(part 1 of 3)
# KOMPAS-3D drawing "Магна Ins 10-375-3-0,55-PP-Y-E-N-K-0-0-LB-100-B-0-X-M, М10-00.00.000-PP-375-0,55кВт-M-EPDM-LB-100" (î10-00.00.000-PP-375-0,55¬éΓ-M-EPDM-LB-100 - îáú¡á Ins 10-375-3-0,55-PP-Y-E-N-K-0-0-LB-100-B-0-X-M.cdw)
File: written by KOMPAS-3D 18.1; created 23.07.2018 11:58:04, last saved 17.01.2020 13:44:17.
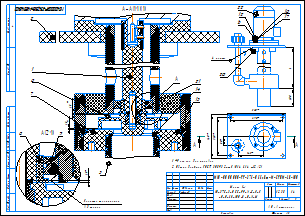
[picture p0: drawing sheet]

Sheet 1: A3, landscape

Document properties: Полное имя файла: ..\М10-00.00.000 - Магна Ins 10-C-N.a3d; Автор: Милов; Масса: 12.3778

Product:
- Part/product: Магна Ins 10-375-3-0,55-PP-Y-E-N-K-0-0-LB-100-B-0-X-M  | designation М10-00.00.000-PP-375-0,55кВт-M-EPDM-LB-100
    Масса: 12.3778
    source file: М10-00.00.000-PP-375-0,55кВт-M-EPDM-LB-100 - Магна Ins 10-375-3-0,55-PP-Y-E-N-K-0-0-LB-100-B-0-X-M.cdw, М10-00.00.000-PP-375-0,55кВт-M-EPDM-LB-100 - Магна Ins 10-375-3-0,55-PP-Y-E-N-K-0-0-LB-100-B-0-X-M.spw
  - Component [detail]: Крышка  | designation М10-00.00.002-01  | pos. 7
      Материал: Полипропилен  ГОСТ 26996-86 (density 900 kg/m3)
      Масса: 0.284697
      Раздел спецификации: Детали
      Форматы листов документа: 4xA4
      Примечание: @100~)4xA4
      Зона: 2A
      source file: ..\М10-00.00.002 - Крышка.cdw, ..\М10-00.00.002 - Крышка.m3d
  - Component [detail]: Импеллер Магна10  | designation М10-00.00.001  | pos. 6  | Масса: 0.169927; Раздел спецификации: Детали; Форматы листов документа: A3; Зона: 2A; source file: ..\М10-00.00.001 - Импеллер Магна10.m3d
  - Component [detail]: Защитная втулка  | designation М10-00.00.003  | pos. 8  | Масса: 0.0193569; Раздел спецификации: Детали; Форматы листов документа: A4; source file: ..\М10-00.00.003 - Защитная втулка.cdw, ..\М10-00.00.003 - Защитная втулка.m3d
  - Component [detail]: Втулка ответная  | designation М10А-00.00.003-01  | pos. 9  | Масса: 0.031838; Раздел спецификации: Детали; Форматы листов документа: A4; Примечание: Заим.; source file: ..\..\..\..\..\..\AquaProf\АкваProf 190\3Д модель\М10А-00.00.003 - Втулка ответная.m3d
  - Component [detail]: Всасывающая трубка 75  | designation L=100  | pos. 5
      Материал: Полипропилен  ГОСТ 26996-86 (density 900 kg/m3)
      Масса: 0.190378
      Раздел спецификации: Детали
      Форматы листов документа: 3xA3
      Примечание: @100~)3xA3
      Зона: 2A
      source file: ..\..\..\..\Магна ins 11\Магна N\3Д\Магна INS 11\Всасывающая трубка 75.m3d, ..\..\..\..\Магна ins 11\Магна N\3Д\Магна INS 11\Чертежи\М11-00.00.004-01 - Крышка.cdw
  - Component [standard]: Кольцо 058-064-36-1-0 ГОСТ 9833-73  | pos. 14
      Материал: Смесь резиновая ИРП-1068 ТУ 38-1051082-86 (density 1280 kg/m3)
      Масса: 0.00194
      Раздел спецификации: Стандартные изделия
      Примечание: EPDM
      Зона: 1A
      Рассекать на разрезах: no
      additional columns: 058-064-36-1-0
  - Component [standard]: Кольцо 125-130-25-1-0 ГОСТ 9833-73  | pos. 15
      Материал: Смесь резиновая ИРП-1068 ТУ 38-1051082-86 (density 1280 kg/m3)
      Масса: 0.00019
      Раздел спецификации: Стандартные изделия
      Примечание: EPDM
      Зона: 1A
      Рассекать на разрезах: no
      additional columns: 125-130-25-1-0
- Part/product: Магна Ins 10-375-3-0,75-PP-Y-V-N-K-0-0-L-0-B-0-X-M  | designation М10-00.00.000-PP-375-0,75кВт-M-Viton
    Масса: 15.6408
  - Component [detail]: Кольцо уплотнительное плоское 10-18-25  | designation Viton  | pos. 93  | Масса: 0.000562973; Раздел спецификации: Прочие изделия
  - Component [assembly]: Корпус полипропилен 375 0,75кВт  / с разъёмной муфтой  | designation М10-00.20.000-PP-375-0,75кВт-M  | pos. 2
      Материал: Полипропилен  ГОСТ 26996-86 (density 900 kg/m3)
      Масса: 5.65999
      Раздел спецификации: Сборочные единицы
      Форматы листов документа: 3xA3
      Примечание: @100~)3xA3@101~)3xA3
      source file: ..\М10-00.20.000 - Корпус.a3d
  - Component [assembly]: Вал  | designation М10-00.15.000-0,75кВт-375  | pos. 1
      Материал: Полипропилен  ГОСТ 26996-86 (density 900 kg/m3)
      Масса: 0.519317
      Раздел спецификации: Сборочные единицы
      Форматы листов документа: 2xA3
      Примечание: @100~)2xA3
      source file: ..\М10-00.15.000 - Вал.a3d
  - Component [detail]: Крышка  | designation М10-00.00.002  | pos. 4
      Материал: Полипропилен  ГОСТ 26996-86 (density 900 kg/m3)
      Масса: 0.324102
      Раздел спецификации: Детали
      Форматы листов документа: 4xA4
      Примечание: @100~)4xA4
      source file: ..\М10-00.00.002 - Крышка.m3d
  - Component [detail]: Импеллер Магна10  | designation М10-00.00.001  | pos. 3  | Масса: 0.169927; Раздел спецификации: Детали; Форматы листов документа: A3; source file: ..\М10-00.00.001 - Импеллер Магна10.m3d
  - Component [detail]: Защитная втулка  | designation М10-00.00.003  | pos. 5  | Масса: 0.0193569; Раздел спецификации: Детали; Форматы листов документа: A4; source file: ..\М10-00.00.003 - Защитная втулка.cdw, ..\М10-00.00.003 - Защитная втулка.m3d
  - Component [detail]: Втулка ответная  | designation М10А-00.00.003-01  | pos. 6  | Масса: 0.031838; Раздел спецификации: Детали; Форматы листов документа: A4; Примечание: Заим.; source file: ..\..\..\..\..\..\AquaProf\АкваProf 190\3Д модель\М10А-00.00.003 - Втулка ответная.m3d
  - Component [standard]: Шайба C.10.21 ГОСТ 11371-78  | qty 8  | pos. 11  | Материал: Сталь 12Х18Н10Т ГОСТ 5632-72 (density 1000 kg/m3); Масса: 0.003438; Раздел спецификации: Стандартные изделия; Рассекать на разрезах: no; additional columns: Сталь 12Х18Н10Т ГОСТ 5632-72
  - Component [standard]: Шайба 10 ГОСТ 6402-70  | qty 4  | pos. 10  | Масса: 0.00201; Раздел спецификации: Стандартные изделия; Примечание: Нерж.; Рассекать на разрезах: no; additional columns: 10; Без указания материала
  - Component [standard]: Гайка М10x1,25-6H(S16) ГОСТ 5915-70  | qty 4  | pos. 9  | Масса: 0.01022; Раздел спецификации: Стандартные изделия; Рассекать на разрезах: no; additional columns: М10x1,25-6H (S16); Сталь 12Х18Н10Т ГОСТ 5632-72
  - Component [standard]: Болт М10x1,25-6gx60 (S16) ГОСТ 7798-70  | qty 4  | pos. 8  | Масса: 0.0467; Раздел спецификации: Стандартные изделия; Рассекать на разрезах: no; additional columns: Сталь 12Х18Н10Т ГОСТ 5632-72
  - Component [detail]: Заглушка @2~25 FV PPR ф. "FV-Plast"  | qty 4  | pos. 12  | Материал: Полипропилен  ГОСТ 26996-86 (density 900 kg/m3); Масса: 0.0161976; Раздел спецификации: Прочие изделия
- Part/product: Магна Ins 10-425-3-0,55-PP-Y-E-N-K-0-0-L-0-B-0-X-R  | designation М10-00.00.000-PP-425-0,55кВт-R-EPDM
    Масса: 11.6152
  - Component [detail]: Втулка ответная  | designation М10А-00.00.003-01  | pos. 6  | Масса: 0.031838; Раздел спецификации: Детали; Форматы листов документа: A4; Примечание: Заим.; source file: ..\..\..\..\..\..\AquaProf\АкваProf 190\3Д модель\М10А-00.00.003 - Втулка ответная.m3d, ..\М10А-00.00.003-01 - Втулка ответная.cdw
  - Component [detail]: Защитная втулка  | designation М10-00.00.003  | pos. 5  | Масса: 0.0193569; Раздел спецификации: Детали; Форматы листов документа: A4; source file: ..\М10-00.00.003 - Защитная втулка.cdw, ..\М10-00.00.003 - Защитная втулка.m3d
  - Component [detail]: Импеллер Магна10  | designation М10-00.00.001  | pos. 3  | Масса: 0.169927; Раздел спецификации: Детали; Форматы листов документа: A3; source file: ..\М10-00.00.001 - Импеллер Магна10.cdw, ..\М10-00.00.001 - Импеллер Магна10.m3d
  - Component [detail]: Крышка  | designation М10-00.00.002  | pos. 4
      Материал: Полипропилен  ГОСТ 26996-86 (density 900 kg/m3)
      Масса: 0.324102
      Раздел спецификации: Детали
      Форматы листов документа: 4xA4
      Примечание: @100~)4xA4
      source file: ..\М10-00.00.002 - Крышка.cdw, ..\М10-00.00.002 - Крышка.m3d
  - Component [assembly]: Вал  | designation М10-00.15.000-0,55кВт-425  | pos. 1
      Материал: Полипропилен  ГОСТ 26996-86 (density 900 kg/m3)
      Масса: 0.580892
      Раздел спецификации: Сборочные единицы
      Форматы листов документа: 2xA3
      Примечание: @100~)2xA3
      source file: ..\М10-00.15.000 - Вал.a3d
  - Component [assembly]: Корпус полипропилен 425 0,55кВт  / с резьбовым переходником  | designation М10-00.20.000-PP-425-0,55кВт-R  | pos. 2  | Материал: Полипропилен  ГОСТ 26996-86 (density 900 kg/m3); Масса: 5.24529; Раздел спецификации: Сборочные единицы; Форматы листов документа: 3xA3; Примечание: @100~)3xA3@101~)3xA3
- Part/product: Магна Ins 10-425-3-0,55-PP-Y-E-N-K-0-0-L-0-B-0-X-M  | designation М10-00.00.000-PP-425-0,55кВт-M-EPDM
    Масса: 12.5317
  - Component [detail]: Втулка ответная  | designation М10А-00.00.003-01  | pos. 6  | Масса: 0.031838; Раздел спецификации: Детали; Форматы листов документа: A4; Примечание: Заим.; source file: ..\..\..\..\..\..\AquaProf\АкваProf 190\3Д модель\М10А-00.00.003 - Втулка ответная.m3d, ..\М10А-00.00.003-01 - Втулка ответная.cdw
  - Component [detail]: Защитная втулка  | designation М10-00.00.003  | pos. 5  | Масса: 0.0193569; Раздел спецификации: Детали; Форматы листов документа: A4; source file: ..\М10-00.00.003 - Защитная втулка.cdw, ..\М10-00.00.003 - Защитная втулка.m3d
  - Component [detail]: Импеллер Магна10  | designation М10-00.00.001  | pos. 3  | Масса: 0.169927; Раздел спецификации: Детали; Форматы листов документа: A3; source file: ..\М10-00.00.001 - Импеллер Магна10.cdw, ..\М10-00.00.001 - Импеллер Магна10.m3d
  - Component [detail]: Крышка  | designation М10-00.00.002  | pos. 4
      Материал: Полипропилен  ГОСТ 26996-86 (density 900 kg/m3)
      Масса: 0.324102
      Раздел спецификации: Детали
      Форматы листов документа: 4xA4
      Примечание: @100~)4xA4
      source file: ..\М10-00.00.002 - Крышка.cdw, ..\М10-00.00.002 - Крышка.m3d
  - Component [assembly]: Вал  | designation М10-00.15.000-0,55кВт-425  | pos. 1
      Материал: Полипропилен  ГОСТ 26996-86 (density 900 kg/m3)
      Масса: 0.580892
      Раздел спецификации: Сборочные единицы
      Форматы листов документа: 2xA3
      Примечание: @100~)2xA3
      source file: ..\М10-00.15.000 - Вал.a3d
  - Component [assembly]: Корпус полипропилен 425 0,55кВт  / с разъёмной муфтой  | designation М10-00.20.000-PP-425-0,55кВт-M  | pos. 2  | Материал: Полипропилен  ГОСТ 26996-86 (density 900 kg/m3); Масса: 6.1618; Раздел спецификации: Сборочные единицы; Форматы листов документа: 3xA3; Примечание: @100~)3xA3@101~)3xA3
- Part/product: Магна Ins 10-PP-425-0,55кВт  | designation М10-00.00.000-PP-425-0,55кВт
    Масса: 11.5823
  - Component [assembly]: Корпус полипропилен 425 0,55кВт  | designation М10-00.20.000-PP-425-0,55кВт  | pos. 2  | Материал: Полипропилен  ГОСТ 26996-86 (density 900 kg/m3); Масса: 5.21242; Раздел спецификации: Сборочные единицы; Форматы листов документа: 3xA3; Примечание: @100~)3xA3@101~)3xA3
  - Component [assembly]: Вал  | designation М10-00.15.000-0,55кВт-425  | pos. 1
      Материал: Полипропилен  ГОСТ 26996-86 (density 900 kg/m3)
      Масса: 0.580892
      Раздел спецификации: Сборочные единицы
      Форматы листов документа: 2xA3
      Примечание: @100~)2xA3
      source file: ..\М10-00.15.000 - Вал.a3d
  - Component [detail]: Крышка  | designation М10-00.00.002  | pos. 4
      Материал: Полипропилен  ГОСТ 26996-86 (density 900 kg/m3)
      Масса: 0.324102
      Раздел спецификации: Детали
      Форматы листов документа: 4xA4
      Примечание: @100~)4xA4
      source file: ..\М10-00.00.002 - Крышка.cdw, ..\М10-00.00.002 - Крышка.m3d
  - Component [detail]: Импеллер Магна10  | designation М10-00.00.001  | pos. 3  | Масса: 0.169927; Раздел спецификации: Детали; Форматы листов документа: A3; source file: ..\М10-00.00.001 - Импеллер Магна10.cdw, ..\М10-00.00.001 - Импеллер Магна10.m3d
  - Component [detail]: Защитная втулка  | designation М10-00.00.003  | pos. 5  | Масса: 0.0193569; Раздел спецификации: Детали; Форматы листов документа: A4; source file: ..\М10-00.00.003 - Защитная втулка.cdw, ..\М10-00.00.003 - Защитная втулка.m3d
  - Component [detail]: Втулка ответная  | designation М10А-00.00.003-01  | pos. 6  | Масса: 0.031838; Раздел спецификации: Детали; Форматы листов документа: A4; Примечание: Заим.; source file: ..\..\..\..\..\..\AquaProf\АкваProf 190\3Д модель\М10А-00.00.003 - Втулка ответная.m3d, ..\М10А-00.00.003-01 - Втулка ответная.cdw
- Part/product: Магна Ins 10-PP-425  | designation М10-00.00.000-PP-425
    Масса: 11.5823
  - Component [detail]: Втулка ответная  | designation М10А-00.00.003-01  | pos. 6  | Масса: 0.031838; Раздел спецификации: Детали; Форматы листов документа: A4; Примечание: Заим.; source file: ..\..\..\..\..\..\AquaProf\АкваProf 190\3Д модель\М10А-00.00.003 - Втулка ответная.m3d, ..\М10А-00.00.003-01 - Втулка ответная.cdw
  - Component [detail]: Защитная втулка  | designation М10-00.00.003  | pos. 5  | Масса: 0.0193569; Раздел спецификации: Детали; Форматы листов документа: A4; source file: ..\М10-00.00.003 - Защитная втулка.cdw, ..\М10-00.00.003 - Защитная втулка.m3d
  - Component [detail]: Импеллер Магна10  | designation М10-00.00.001  | pos. 3  | Масса: 0.169927; Раздел спецификации: Детали; Форматы листов документа: A3; source file: ..\М10-00.00.001 - Импеллер Магна10.cdw, ..\М10-00.00.001 - Импеллер Магна10.m3d
  - Component [detail]: Крышка  | designation М10-00.00.002  | pos. 4
      Материал: Полипропилен  ГОСТ 26996-86 (density 900 kg/m3)
      Масса: 0.324102
      Раздел спецификации: Детали
      Форматы листов документа: 4xA4
      Примечание: @100~)4xA4
      source file: ..\М10-00.00.002 - Крышка.cdw, ..\М10-00.00.002 - Крышка.m3d
  - Component [assembly]: Вал  | designation М10-00.15.000-0,55кВт-425  | pos. 1
      Материал: Полипропилен  ГОСТ 26996-86 (density 900 kg/m3)
      Масса: 0.580892
      Раздел спецификации: Сборочные единицы
      Форматы листов документа: 2xA3
      Примечание: @100~)2xA3
      source file: ..\М10-00.15.000 - Вал.a3d
- Part/product: Магна Ins 10-375-3-0,75-PP-Y-E-N-K-0-0-L-0-B-0-X-R  | designation М10-00.00.000-PP-375-0,75кВт-R-EPDM
    Масса: 14.7243
  - Component [detail]: Заглушка @2~25 FV PPR ф. "FV-Plast"  | qty 4  | pos. 12  | Материал: Полипропилен  ГОСТ 26996-86 (density 900 kg/m3); Масса: 0.0161976; Раздел спецификации: Прочие изделия
  - Component [standard]: Болт М10x1,25-6gx60 (S16) ГОСТ 7798-70  | qty 4  | pos. 8  | Масса: 0.0467; Раздел спецификации: Стандартные изделия; Рассекать на разрезах: no; additional columns: Сталь 12Х18Н10Т ГОСТ 5632-72
  - Component [standard]: Гайка М10x1,25-6H(S16) ГОСТ 5915-70  | qty 4  | pos. 9  | Масса: 0.01022; Раздел спецификации: Стандартные изделия; Рассекать на разрезах: no; additional columns: М10x1,25-6H (S16); Сталь 12Х18Н10Т ГОСТ 5632-72
  - Component [standard]: Шайба 10 ГОСТ 6402-70  | qty 4  | pos. 10  | Масса: 0.00201; Раздел спецификации: Стандартные изделия; Примечание: Нерж.; Рассекать на разрезах: no; additional columns: 10; Без указания материала
  - Component [standard]: Шайба C.10.21 ГОСТ 11371-78  | qty 8  | pos. 11  | Материал: Сталь 12Х18Н10Т ГОСТ 5632-72 (density 1000 kg/m3); Масса: 0.003438; Раздел спецификации: Стандартные изделия; Рассекать на разрезах: no; additional columns: Сталь 12Х18Н10Т ГОСТ 5632-72
  - Component [detail]: Втулка ответная  | designation М10А-00.00.003-01  | pos. 6  | Масса: 0.031838; Раздел спецификации: Детали; Форматы листов документа: A4; Примечание: Заим.; source file: ..\..\..\..\..\..\AquaProf\АкваProf 190\3Д модель\М10А-00.00.003 - Втулка ответная.m3d, ..\М10А-00.00.003-01 - Втулка ответная.cdw
  - Component [detail]: Защитная втулка  | designation М10-00.00.003  | pos. 5  | Масса: 0.0193569; Раздел спецификации: Детали; Форматы листов документа: A4; source file: ..\М10-00.00.003 - Защитная втулка.cdw, ..\М10-00.00.003 - Защитная втулка.m3d
  - Component [detail]: Импеллер Магна10  | designation М10-00.00.001  | pos. 3  | Масса: 0.169927; Раздел спецификации: Детали; Форматы листов документа: A3; source file: ..\М10-00.00.001 - Импеллер Магна10.cdw, ..\М10-00.00.001 - Импеллер Магна10.m3d
  - Component [detail]: Крышка  | designation М10-00.00.002  | pos. 4
      Материал: Полипропилен  ГОСТ 26996-86 (density 900 kg/m3)
      Масса: 0.324102
      Раздел спецификации: Детали
      Форматы листов документа: 4xA4
      Примечание: @100~)4xA4
      source file: ..\М10-00.00.002 - Крышка.cdw, ..\М10-00.00.002 - Крышка.m3d
  - Component [assembly]: Вал  | designation М10-00.15.000-0,75кВт  | pos. 1  | Материал: Полипропилен  ГОСТ 26996-86 (density 900 kg/m3); Масса: 0.807009; Раздел спецификации: Сборочные единицы; Форматы листов документа: 2xA3; Примечание: @100~)2xA3
  - Component [assembly]: Корпус полипропилен 375 0,75кВт  / с резьбовым переходником  | designation М10-00.20.000-PP-375-0,75кВт-R  | pos. 2  | Материал: Полипропилен  ГОСТ 26996-86 (density 900 kg/m3); Масса: 4.74348; Раздел спецификации: Сборочные единицы; Форматы листов документа: 3xA3; Примечание: @100~)3xA3@101~)3xA3
- Part/product: Магна Ins 10-375-3-0,75-PP-Y-E-N-K-0-0-L-0-B-0-X-M  | designation М10-00.00.000-PP-375-0,75кВт-M-EPDM
    Масса: 15.6408
  - Component [detail]: Заглушка @2~25 FV PPR ф. "FV-Plast"  | qty 4  | pos. 12  | Материал: Полипропилен  ГОСТ 26996-86 (density 900 kg/m3); Масса: 0.0161976; Раздел спецификации: Прочие изделия
  - Component [standard]: Болт М10x1,25-6gx60 (S16) ГОСТ 7798-70  | qty 4  | pos. 8  | Масса: 0.0467; Раздел спецификации: Стандартные изделия; Рассекать на разрезах: no; additional columns: Сталь 12Х18Н10Т ГОСТ 5632-72
  - Component [standard]: Гайка М10x1,25-6H(S16) ГОСТ 5915-70  | qty 4  | pos. 9  | Масса: 0.01022; Раздел спецификации: Стандартные изделия; Рассекать на разрезах: no; additional columns: М10x1,25-6H (S16); Сталь 12Х18Н10Т ГОСТ 5632-72
  - Component [standard]: Шайба 10 ГОСТ 6402-70  | qty 4  | pos. 10  | Масса: 0.00201; Раздел спецификации: Стандартные изделия; Примечание: Нерж.; Рассекать на разрезах: no; additional columns: 10; Без указания материала
  - Component [standard]: Шайба C.10.21 ГОСТ 11371-78  | qty 8  | pos. 11  | Материал: Сталь 12Х18Н10Т ГОСТ 5632-72 (density 1000 kg/m3); Масса: 0.003438; Раздел спецификации: Стандартные изделия; Рассекать на разрезах: no; additional columns: Сталь 12Х18Н10Т ГОСТ 5632-72
  - Component [detail]: Втулка ответная  | designation М10А-00.00.003-01  | pos. 6  | Масса: 0.031838; Раздел спецификации: Детали; Форматы листов документа: A4; Примечание: Заим.; source file: ..\..\..\..\..\..\AquaProf\АкваProf 190\3Д модель\М10А-00.00.003 - Втулка ответная.m3d, ..\М10А-00.00.003-01 - Втулка ответная.cdw
  - Component [detail]: Защитная втулка  | designation М10-00.00.003  | pos. 5  | Масса: 0.0193569; Раздел спецификации: Детали; Форматы листов документа: A4; source file: ..\М10-00.00.003 - Защитная втулка.cdw, ..\М10-00.00.003 - Защитная втулка.m3d
  - Component [detail]: Импеллер Магна10  | designation М10-00.00.001  | pos. 3  | Масса: 0.169927; Раздел спецификации: Детали; Форматы листов документа: A3; source file: ..\М10-00.00.001 - Импеллер Магна10.cdw, ..\М10-00.00.001 - Импеллер Магна10.m3d
  - Component [detail]: Крышка  | designation М10-00.00.002  | pos. 4
      Материал: Полипропилен  ГОСТ 26996-86 (density 900 kg/m3)
      Масса: 0.324102
      Раздел спецификации: Детали
      Форматы листов документа: 4xA4
      Примечание: @100~)4xA4
      source file: ..\М10-00.00.002 - Крышка.cdw, ..\М10-00.00.002 - Крышка.m3d
  - Component [assembly]: Вал  | designation М10-00.15.000-0,75кВт-375  | pos. 1
      Материал: Полипропилен  ГОСТ 26996-86 (density 900 kg/m3)
      Масса: 0.519317
      Раздел спецификации: Сборочные единицы
      Форматы листов документа: 2xA3
      Примечание: @100~)2xA3
      source file: ..\М10-00.15.000 - Вал.a3d
  - Component [assembly]: Корпус полипропилен 375 0,75кВт  / с разъёмной муфтой  | designation М10-00.20.000-PP-375-0,75кВт-M  | pos. 2
      Материал: Полипропилен  ГОСТ 26996-86 (density 900 kg/m3)
      Масса: 5.65999
      Раздел спецификации: Сборочные единицы
      Форматы листов документа: 3xA3
      Примечание: @100~)3xA3@101~)3xA3
      source file: ..\М10-00.20.000 - Корпус.a3d
- Part/product: Магна Ins 10-PP-375-0,75кВт  | designation М10-00.00.000-PP-375-0,75кВт
    Масса: 14.6914
  - Component [detail]: Электродвигатель 3ф. АИР 71А2 / 380В 0,75кВт 3000 об/мин 3081 DRIVE IEK / арт.DRV071-A2-000-8-3030  | pos. 356  | Масса: 8.3; Раздел спецификации: Прочие изделия; Примечание: IP55; source file: ..\..\..\..\..\..\1 ПКИ 3D\Двигатели\АИР\Электродвигатель 3ф. АИР 71А2 380В 0,75кВт 3000об_мин 3081 DRIVE IEK.m3d
  - Component [assembly]: Корпус полипропилен 375 0,75кВт  | designation М10-00.20.000-PP-375-0,75кВт  | pos. 2  | Материал: Полипропилен  ГОСТ 26996-86 (density 900 kg/m3); Масса: 4.71061; Раздел спецификации: Сборочные единицы; Форматы листов документа: 3xA3; Примечание: @100~)3xA3@101~)3xA3
  - Component [assembly]: Вал  | designation М10-00.15.000-0,75кВт  | pos. 1  | Материал: Полипропилен  ГОСТ 26996-86 (density 900 kg/m3); Масса: 0.807009; Раздел спецификации: Сборочные единицы; Форматы листов документа: 2xA3; Примечание: @100~)2xA3
  - Component [detail]: Крышка  | designation М10-00.00.002  | pos. 4
      Материал: Полипропилен  ГОСТ 26996-86 (density 900 kg/m3)
      Масса: 0.324102
      Раздел спецификации: Детали
      Форматы листов документа: 4xA4
      Примечание: @100~)4xA4
      source file: ..\М10-00.00.002 - Крышка.cdw, ..\М10-00.00.002 - Крышка.m3d
  - Component [detail]: Импеллер Магна10  | designation М10-00.00.001  | pos. 3  | Масса: 0.169927; Раздел спецификации: Детали; Форматы листов документа: A3; source file: ..\М10-00.00.001 - Импеллер Магна10.cdw, ..\М10-00.00.001 - Импеллер Магна10.m3d
  - Component [detail]: Защитная втулка  | designation М10-00.00.003  | pos. 5  | Масса: 0.0193569; Раздел спецификации: Детали; Форматы листов документа: A4; source file: ..\М10-00.00.003 - Защитная втулка.cdw, ..\М10-00.00.003 - Защитная втулка.m3d
  - Component [detail]: Втулка ответная  | designation М10А-00.00.003-01  | pos. 6  | Масса: 0.031838; Раздел спецификации: Детали; Форматы листов документа: A4; Примечание: Заим.; source file: ..\..\..\..\..\..\AquaProf\АкваProf 190\3Д модель\М10А-00.00.003 - Втулка ответная.m3d, ..\М10А-00.00.003-01 - Втулка ответная.cdw
  - Component [standard]: Шайба C.10.21 ГОСТ 11371-78  | qty 8  | pos. 11  | Материал: Сталь 12Х18Н10Т ГОСТ 5632-72 (density 1000 kg/m3); Масса: 0.003438; Раздел спецификации: Стандартные изделия; Рассекать на разрезах: no; additional columns: Сталь 12Х18Н10Т ГОСТ 5632-72
  - Component [standard]: Шайба 10 ГОСТ 6402-70  | qty 4  | pos. 10  | Масса: 0.00201; Раздел спецификации: Стандартные изделия; Примечание: Нерж.; Рассекать на разрезах: no; additional columns: 10; Без указания материала
  - Component [standard]: Гайка М10x1,25-6H(S16) ГОСТ 5915-70  | qty 4  | pos. 9  | Масса: 0.01022; Раздел спецификации: Стандартные изделия; Рассекать на разрезах: no; additional columns: М10x1,25-6H (S16); Сталь 12Х18Н10Т ГОСТ 5632-72
  - Component [standard]: Болт М10x1,25-6gx60 (S16) ГОСТ 7798-70  | qty 4  | pos. 8  | Масса: 0.0467; Раздел спецификации: Стандартные изделия; Рассекать на разрезах: no; additional columns: Сталь 12Х18Н10Т ГОСТ 5632-72
  - Component [detail]: Заглушка @2~25 FV PPR ф. "FV-Plast"  | qty 4  | pos. 12  | Материал: Полипропилен  ГОСТ 26996-86 (density 900 kg/m3); Масса: 0.0161976; Раздел спецификации: Прочие изделия
- Part/product: Магна Ins 10-375-3-0,55-PP-Y-E-N-K-0-0-L-0-B-0-X-M  | designation М10-00.00.000-PP-375-0,55кВт-M-EPDM
    Масса: 12.2247
  - Component [detail]: Электродвигатель АИР 63В2 / IM 3081 0,55кВт 3000 об/мин  | pos. 14  | Масса: 5.02; Раздел спецификации: Прочие изделия; Примечание: IP55; source file: ..\..\..\..\..\..\1 ПКИ 3D\Двигатели\АИР\Электродвигатель АИР 63В2 IM 3081 0,55кВт 3000 об..m3d
  - Component [detail]: Втулка ответная  | designation М10А-00.00.003-01  | pos. 6  | Масса: 0.031838; Раздел спецификации: Детали; Форматы листов документа: A4; Примечание: Заим.; source file: ..\..\..\..\..\..\AquaProf\АкваProf 190\3Д модель\М10А-00.00.003 - Втулка ответная.m3d, ..\М10А-00.00.003-01 - Втулка ответная.cdw
  - Component [detail]: Защитная втулка  | designation М10-00.00.003  | pos. 5  | Масса: 0.0193569; Раздел спецификации: Детали; Форматы листов документа: A4; source file: ..\М10-00.00.003 - Защитная втулка.cdw, ..\М10-00.00.003 - Защитная втулка.m3d
  - Component [detail]: Импеллер Магна10  | designation М10-00.00.001  | pos. 3  | Масса: 0.169927; Раздел спецификации: Детали; Форматы листов документа: A3; source file: ..\М10-00.00.001 - Импеллер Магна10.cdw, ..\М10-00.00.001 - Импеллер Магна10.m3d
  - Component [detail]: Крышка  | designation М10-00.00.002  | pos. 4
      Материал: Полипропилен  ГОСТ 26996-86 (density 900 kg/m3)
      Масса: 0.324102
      Раздел спецификации: Детали
      Форматы листов документа: 4xA4
      Примечание: @100~)4xA4
      source file: ..\М10-00.00.002 - Крышка.cdw, ..\М10-00.00.002 - Крышка.m3d
  - Component [assembly]: Вал  | designation М10-00.15.000-0,55кВт-375  | pos. 1
      Материал: Полипропилен  ГОСТ 26996-86 (density 900 kg/m3)
      Масса: 0.519317
      Раздел спецификации: Сборочные единицы
      Форматы листов документа: 2xA3
      Примечание: @100~)2xA3
      source file: ..\М10-00.15.000 - Вал.a3d
  - Component [assembly]: Корпус полипропилен 375 0,55 кВт  / с разъёмной муфтой  | designation М10-00.20.000-PP-375-0,55кВт-M  | pos. 2
      Материал: Полипропилен  ГОСТ 26996-86 (density 900 kg/m3)
      Масса: 5.91637
      Раздел спецификации: Сборочные единицы
      Форматы листов документа: 3xA3
      Примечание: @100~)3xA3@101~)3xA3
      source file: ..\М10-00.20.000 - Корпус.a3d
- Part/product: Магна Ins 10-C-N  | designation М10-00.00.000
    Масса: 11.2753
    source file: ..\М10-00.00.000 - Магна Ins 10-C-N.cdw
  - Component: Шайба C.10.21 ГОСТ 11371-78  | pos. 11  | Материал: Сталь 12Х18Н10Т ГОСТ 5632-72; Масса: 0.0034; Раздел спецификации: Стандартные изделия
  - Component [detail]: Заглушка @2~20 FV PPR ф. "FV-Plast"  | qty 4  | pos. 12  | Масса: 0.0187746; Раздел спецификации: Прочие изделия; source file: ..\Заглушка ф20 FV PPR ф. FV-Plast.m3d
  - Component [standard]: Болт М8-6gx55.21.12Х18Н10Т ГОСТ 7798-70  | qty 4  | pos. 8  | Материал: Сталь 12Х18Н10Т ГОСТ 5632-72 (density 1000 kg/m3); Масса: 0.02699; Раздел спецификации: Стандартные изделия; additional columns: Сталь 12Х18Н10Т ГОСТ 5632-72; source file: C:\Program Files\ASCON\KOMPAS-3D v18\Libs\PartLib\DATA\VAULT\methods\kompas\3d\PLib_Bolt_1_900.m3d
  - Component [standard]: Гайка М8-6H.21.12Х18Н10Т ГОСТ 5915-70  | qty 4  | pos. 9  | Материал: Сталь 12Х18Н10Т ГОСТ 5632-72 (density 1000 kg/m3); Масса: 0.005548; Раздел спецификации: Стандартные изделия; additional columns: Сталь 12Х18Н10Т ГОСТ 5632-72; source file: C:\Program Files\ASCON\KOMPAS-3D v18\Libs\PartLib\DATA\VAULT\methods\kompas\3d\PLib_Nut_OST92_900.m3d
  - Component [standard]: Шайба 8 ГОСТ 6402-70  | qty 4  | pos. 10  | Масса: 0.001034; Раздел спецификации: Стандартные изделия; Примечание: Нерж.; additional columns: 8; Без указания материала; source file: C:\Program Files\ASCON\KOMPAS-3D v18\Libs\PartLib\DATA\VAULT\methods\kompas\3d\PLib_Washer_2_712.m3d
  - Component [standard]: Шайба C.8.21 ГОСТ 11371-78  | qty 8  | pos. 11  | Материал: Сталь 12Х18Н10Т ГОСТ 5632-72 (density 1000 kg/m3); Масса: 0.001725; Раздел спецификации: Стандартные изделия; additional columns: Сталь 12Х18Н10Т ГОСТ 5632-72; source file: C:\Program Files\ASCON\KOMPAS-3D v18\Libs\PartLib\DATA\VAULT\methods\kompas\3d\PLib_Washer_1_712.m3d
  - Component [detail]: Втулка ответная  | designation М10А-00.00.003-01  | pos. 6  | Масса: 0.031838; Раздел спецификации: Детали; Форматы листов документа: A4; Примечание: Заим.; source file: ..\..\..\..\..\..\AquaProf\АкваProf 190\3Д модель\М10А-00.00.003 - Втулка ответная.m3d, ..\М10А-00.00.003-01 - Втулка ответная.cdw
  - Component [detail]: Защитная втулка  | designation М10-00.00.003  | pos. 5  | Масса: 0.0193569; Раздел спецификации: Детали; Форматы листов документа: A4; source file: ..\М10-00.00.003 - Защитная втулка.cdw, ..\М10-00.00.003 - Защитная втулка.m3d
  - Component [detail]: Импеллер Магна10  | designation М10-00.00.001  | pos. 3  | Масса: 0.169927; Раздел спецификации: Детали; Форматы листов документа: A3; source file: ..\М10-00.00.001 - Импеллер Магна10.cdw, ..\М10-00.00.001 - Импеллер Магна10.m3d
  - Component [detail]: Крышка  | designation М10-00.00.002  | pos. 4
      Материал: Полипропилен  ГОСТ 26996-86 (density 900 kg/m3)
      Масса: 0.324102
      Раздел спецификации: Детали
      Форматы листов документа: 4xA4
      Примечание: @100~)4xA4
      source file: ..\М10-00.00.002 - Крышка.cdw, ..\М10-00.00.002 - Крышка.m3d
  - Component [assembly]: Вал  | designation М10-00.15.000  | pos. 1
      Материал: Полипропилен  ГОСТ 26996-86 (density 900 kg/m3)
      Масса: 0.519317
      Раздел спецификации: Сборочные единицы
      Форматы листов документа: 2xA3
      Примечание: @100~)2xA3
      source file: ..\М10-00.15.000 - Вал.a3d, ..\М10-00.15.000 - Вал.cdw
  - Component [detail]: Электродвигатель  / IM 3081 3000 об/мин IP55  | pos. 14  | Масса: 5.02; Раздел спецификации: Прочие изделия; Примечание: См. заказ; source file: ..\..\..\..\..\..\1 ПКИ 3D\Двигатели\АИР\Двигатель без габарита в СП\Электродвигатель АИР 63В2 IM 3081 0,55кВт 3000 об..m3d
  - Component [assembly]: Корпус  | designation М10-00.20.000  | pos. 2
      Материал: Полипропилен  ГОСТ 26996-86 (density 900 kg/m3)
      Масса: 4.96698
      Раздел спецификации: Сборочные единицы
      Форматы листов документа: 3xA3
      Примечание: @100~)3xA3@101~)3xA3
      source file: ..\М10-00.20.000 - Корпус.a3d, ..\М10-00.20.000 - Корпус.cdw
  - Component [detail]: Кольцо уплотнительное плоское 10-18-25  | designation EPDM  | pos. 93  | Масса: 0.000562973; Раздел спецификации: Прочие изделия; source file: ..\..\..\..\..\..\1 ПКИ 3D\РТИ\Кольца уплотнительные  плоские\Кольцо уплотнительное плоское 10-18-25 ЕPDM.m3d
- Part/product: Магна Ins 10-PP  | designation М10-00.00.000-PP
    Масса: 11.2753
  - Component [assembly]: Вал  | designation М10-00.15.000  | pos. 1
      Материал: Полипропилен  ГОСТ 26996-86 (density 900 kg/m3)
      Масса: 0.519317
      Раздел спецификации: Сборочные единицы
      Форматы листов документа: 2xA3
      Примечание: @100~)2xA3
      source file: ..\М10-00.15.000 - Вал.a3d, ..\М10-00.15.000 - Вал.cdw
  - Component [detail]: Крышка  | designation М10-00.00.002  | pos. 4
      Материал: Полипропилен  ГОСТ 26996-86 (density 900 kg/m3)
      Масса: 0.324102
      Раздел спецификации: Детали
      Форматы листов документа: 4xA4
      Примечание: @100~)4xA4
      source file: ..\М10-00.00.002 - Крышка.cdw, ..\М10-00.00.002 - Крышка.m3d
  - Component [detail]: Защитная втулка  | designation М10-00.00.003  | pos. 5  | Масса: 0.0193569; Раздел спецификации: Детали; Форматы листов документа: A4; source file: ..\М10-00.00.003 - Защитная втулка.cdw, ..\М10-00.00.003 - Защитная втулка.m3d
  - Component [detail]: Втулка ответная  | designation М10А-00.00.003-01  | pos. 6  | Масса: 0.031838; Раздел спецификации: Детали; Форматы листов документа: A4; Примечание: Заим.; source file: ..\..\..\..\..\..\AquaProf\АкваProf 190\3Д модель\М10А-00.00.003 - Втулка ответная.m3d, ..\М10А-00.00.003-01 - Втулка ответная.cdw
- Part/product: Магна Ins 10-PP-375  | designation М10-00.00.000-PP-375
    Масса: 11.2753
  - Component [detail]: Втулка ответная  | designation М10А-00.00.003-01  | pos. 6  | Масса: 0.031838; Раздел спецификации: Детали; Форматы листов документа: A4; Примечание: Заим.; source file: ..\..\..\..\..\..\AquaProf\АкваProf 190\3Д модель\М10А-00.00.003 - Втулка ответная.m3d, ..\М10А-00.00.003-01 - Втулка ответная.cdw
  - Component [detail]: Защитная втулка  | designation М10-00.00.003  | pos. 5  | Масса: 0.0193569; Раздел спецификации: Детали; Форматы листов документа: A4; source file: ..\М10-00.00.003 - Защитная втулка.cdw, ..\М10-00.00.003 - Защитная втулка.m3d
  - Component [detail]: Импеллер Магна10  | designation М10-00.00.001  | pos. 3  | Масса: 0.169927; Раздел спецификации: Детали; Форматы листов документа: A3; source file: ..\М10-00.00.001 - Импеллер Магна10.cdw, ..\М10-00.00.001 - Импеллер Магна10.m3d
  - Component [detail]: Крышка  | designation М10-00.00.002  | pos. 4
      Материал: Полипропилен  ГОСТ 26996-86 (density 900 kg/m3)
      Масса: 0.324102
      Раздел спецификации: Детали
      Форматы листов документа: 4xA4
      Примечание: @100~)4xA4
      source file: ..\М10-00.00.002 - Крышка.cdw, ..\М10-00.00.002 - Крышка.m3d
  - Component [assembly]: Вал  | designation М10-00.15.000  | pos. 1
      Материал: Полипропилен  ГОСТ 26996-86 (density 900 kg/m3)
      Масса: 0.519317
      Раздел спецификации: Сборочные единицы
      Форматы листов документа: 2xA3
      Примечание: @100~)2xA3
      source file: ..\М10-00.15.000 - Вал.a3d, ..\М10-00.15.000 - Вал.cdw
- Part/product: Магна Ins 10-PP-375-0,55кВт  | designation М10-00.00.000-PP-375-0,55кВт
    Масса: 11.2753
  - Component [detail]: Электродвигатель АИР 63В2 / IM 3081 0,55кВт 3000 об/мин  | pos. 321  | Масса: 5.02; Раздел спецификации: Прочие изделия; Примечание: IP55; source file: ..\..\..\..\..\..\1 ПКИ 3D\Двигатели\АИР\Электродвигатель АИР 63В2 IM 3081 0,55кВт 3000 об..m3d
  - Component [assembly]: Корпус полипропилен 375 0,55 кВт  | designation М10-00.20.000-PP-375-0,55кВт  | pos. 2  | Материал: Полипропилен  ГОСТ 26996-86 (density 900 kg/m3); Масса: 4.96698; Раздел спецификации: Сборочные единицы; Форматы листов документа: 3xA3; Примечание: @100~)3xA3@101~)3xA3
  - Component [assembly]: Вал  | designation М10-00.15.000-0,55кВт-375  | pos. 1
      Материал: Полипропилен  ГОСТ 26996-86 (density 900 kg/m3)
      Масса: 0.519317
      Раздел спецификации: Сборочные единицы
      Форматы листов документа: 2xA3
      Примечание: @100~)2xA3
      source file: ..\М10-00.15.000 - Вал.a3d
  - Component [detail]: Крышка  | designation М10-00.00.002  | pos. 4
      Материал: Полипропилен  ГОСТ 26996-86 (density 900 kg/m3)
      Масса: 0.324102
      Раздел спецификации: Детали
      Форматы листов документа: 4xA4
      Примечание: @100~)4xA4
      source file: ..\М10-00.00.002 - Крышка.cdw, ..\М10-00.00.002 - Крышка.m3d
  - Component [detail]: Импеллер Магна10  | designation М10-00.00.001  | pos. 3  | Масса: 0.169927; Раздел спецификации: Детали; Форматы листов документа: A3; source file: ..\М10-00.00.001 - Импеллер Магна10.cdw, ..\М10-00.00.001 - Импеллер Магна10.m3d
  - Component [detail]: Защитная втулка  | designation М10-00.00.003  | pos. 5  | Масса: 0.0193569; Раздел спецификации: Детали; Форматы листов документа: A4; source file: ..\М10-00.00.003 - Защитная втулка.cdw, ..\М10-00.00.003 - Защитная втулка.m3d
  - Component [detail]: Втулка ответная  | designation М10А-00.00.003-01  | pos. 6  | Масса: 0.031838; Раздел спецификации: Детали; Форматы листов документа: A4; Примечание: Заим.; source file: ..\..\..\..\..\..\AquaProf\АкваProf 190\3Д модель\М10А-00.00.003 - Втулка ответная.m3d, ..\М10А-00.00.003-01 - Втулка ответная.cdw
- Part/product: Магна Ins 10-375-3-0,55-PP-Y-E-N-K-0-0-L-0-B-0-X-R  | designation М10-00.00.000-PP-375-0,55кВт-R-EPDM
    Масса: 11.3082
  - Component [detail]: Электродвигатель АИР 63В2 / IM 3081 0,55кВт 3000 об/мин  | pos. 14  | Масса: 5.02; Раздел спецификации: Прочие изделия; Примечание: IP55; source file: ..\..\..\..\..\..\1 ПКИ 3D\Двигатели\АИР\Электродвигатель АИР 63В2 IM 3081 0,55кВт 3000 об..m3d
  - Component [detail]: Заглушка @2~20 FV PPR ф. "FV-Plast"  | pos. 12  | Масса: 0.0187746; Раздел спецификации: Прочие изделия; source file: ..\Заглушка ф20 FV PPR ф. FV-Plast.m3d
  - Component [detail]: Втулка ответная  | designation М10А-00.00.003-01  | pos. 6  | Масса: 0.031838; Раздел спецификации: Детали; Форматы листов документа: A4; Примечание: Заим.; source file: ..\..\..\..\..\..\AquaProf\АкваProf 190\3Д модель\М10А-00.00.003 - Втулка ответная.m3d, ..\М10А-00.00.003-01 - Втулка ответная.cdw
  - Component [detail]: Защитная втулка  | designation М10-00.00.003  | pos. 5  | Масса: 0.0193569; Раздел спецификации: Детали; Форматы листов документа: A4; source file: ..\М10-00.00.003 - Защитная втулка.cdw, ..\М10-00.00.003 - Защитная втулка.m3d
  - Component [detail]: Импеллер Магна10  | designation М10-00.00.001  | pos. 3  | Масса: 0.169927; Раздел спецификации: Детали; Форматы листов документа: A3; source file: ..\М10-00.00.001 - Импеллер Магна10.cdw, ..\М10-00.00.001 - Импеллер Магна10.m3d
  - Component [detail]: Крышка  | designation М10-00.00.002  | pos. 4
      Материал: Полипропилен  ГОСТ 26996-86 (density 900 kg/m3)
      Масса: 0.324102
      Раздел спецификации: Детали
      Форматы листов документа: 4xA4
      Примечание: @100~)4xA4
      source file: ..\М10-00.00.002 - Крышка.cdw, ..\М10-00.00.002 - Крышка.m3d
  - Component [assembly]: Вал  | designation М10-00.15.000-0,55кВт-375  | pos. 1
      Материал: Полипропилен  ГОСТ 26996-86 (density 900 kg/m3)
      Масса: 0.519317
      Раздел спецификации: Сборочные единицы
      Форматы листов документа: 2xA3
      Примечание: @100~)2xA3
      source file: ..\М10-00.15.000 - Вал.a3d
  - Component [assembly]: Корпус полипропилен 375 0,55 кВт  / с резьбовым переходником  | designation М10-00.20.000-PP-375-0,55кВт-R  | pos. 2
      Материал: Полипропилен  ГОСТ 26996-86 (density 900 kg/m3)
      Масса: 4.99986
      Раздел спецификации: Сборочные единицы
      Форматы листов документа: 3xA3
      Примечание: @100~)3xA3@101~)3xA3
      source file: ..\М10-00.20.000 - Корпус.a3d
  - Component [detail]: Кольцо уплотнительное плоское 10-18-25  | designation EPDM  | pos. 13  | Масса: 0.000562973; Раздел спецификации: Прочие изделия; source file: ..\..\..\..\..\..\1 ПКИ 3D\РТИ\Кольца уплотнительные  плоские\Кольцо уплотнительное плоское 10-18-25 ЕPDM.m3d
- Part/product: Магна Ins 10-PP-375-1,1кВт  | designation М10-00.00.000-PP-375-1,1кВт
    Масса: 14.4037
  - Component [detail]: Электродвигатель / АИР 71B2 IM 3081 IP55 ф."Элком"  | pos. 14  | Масса: 8.3; Раздел спецификации: Прочие изделия; Примечание: См. заказ
  - Component [assembly]: Вал  | designation М10-00.15.000  | pos. 1
      Материал: Полипропилен  ГОСТ 26996-86 (density 900 kg/m3)
      Масса: 0.519317
      Раздел спецификации: Сборочные единицы
      Форматы листов документа: 2xA3
      Примечание: @100~)2xA3
      source file: ..\М10-00.15.000 - Вал.a3d, ..\М10-00.15.000 - Вал.cdw
  - Component [detail]: Крышка  | designation М10-00.00.002  | pos. 4
      Материал: Полипропилен  ГОСТ 26996-86 (density 900 kg/m3)
      Масса: 0.324102
      Раздел спецификации: Детали
      Форматы листов документа: 4xA4
      Примечание: @100~)4xA4
      source file: ..\М10-00.00.002 - Крышка.cdw, ..\М10-00.00.002 - Крышка.m3d
  - Component [detail]: Импеллер Магна10  | designation М10-00.00.001  | pos. 3  | Масса: 0.169927; Раздел спецификации: Детали; Форматы листов документа: A3; source file: ..\М10-00.00.001 - Импеллер Магна10.cdw, ..\М10-00.00.001 - Импеллер Магна10.m3d
  - Component [detail]: Защитная втулка  | designation М10-00.00.003  | pos. 5  | Масса: 0.0193569; Раздел спецификации: Детали; Форматы листов документа: A4; source file: ..\М10-00.00.003 - Защитная втулка.cdw, ..\М10-00.00.003 - Защитная втулка.m3d
  - Component [detail]: Втулка ответная  | designation М10А-00.00.003-01  | pos. 6  | Масса: 0.031838; Раздел спецификации: Детали; Форматы листов документа: A4; Примечание: Заим.; source file: ..\..\..\..\..\..\AquaProf\АкваProf 190\3Д модель\М10А-00.00.003 - Втулка ответная.m3d, ..\М10А-00.00.003-01 - Втулка ответная.cdw
  - Component [standard]: Шайба C.10.21 ГОСТ 11371-78  | qty 8  | pos. 11  | Материал: Сталь 12Х18Н10Т ГОСТ 5632-72 (density 1000 kg/m3); Масса: 0.003438; Раздел спецификации: Стандартные изделия; Рассекать на разрезах: no; additional columns: Сталь 12Х18Н10Т ГОСТ 5632-72
  - Component [standard]: Шайба 10 ГОСТ 6402-70  | qty 4  | pos. 10  | Масса: 0.00201; Раздел спецификации: Стандартные изделия; Примечание: Нерж.; Рассекать на разрезах: no; additional columns: 10; Без указания материала
  - Component [standard]: Гайка М10x1,25-6H(S16) ГОСТ 5915-70  | qty 4  | pos. 9  | Масса: 0.01022; Раздел спецификации: Стандартные изделия; Рассекать на разрезах: no; additional columns: М10x1,25-6H (S16); Сталь 12Х18Н10Т ГОСТ 5632-72
  - Component [standard]: Болт М10x1,25-6gx60 (S16) ГОСТ 7798-70  | qty 4  | pos. 8  | Масса: 0.0467; Раздел спецификации: Стандартные изделия; Рассекать на разрезах: no; additional columns: Сталь 12Х18Н10Т ГОСТ 5632-72
  - Component [detail]: Заглушка @2~25 FV PPR ф. "FV-Plast"  | qty 4  | pos. 12  | Материал: Полипропилен  ГОСТ 26996-86 (density 900 kg/m3); Масса: 0.0161976; Раздел спецификации: Прочие изделия
- Part/product: Магна Ins 10-PP-475  | designation М10-00.00.000-PP-475
    Масса: 11.8893
  - Component [detail]: Втулка ответная  | designation М10А-00.00.003-01  | pos. 6  | Масса: 0.031838; Раздел спецификации: Детали; Форматы листов документа: A4; Примечание: Заим.; source file: ..\..\..\..\..\..\AquaProf\АкваProf 190\3Д модель\М10А-00.00.003 - Втулка ответная.m3d, ..\М10А-00.00.003-01 - Втулка ответная.cdw
  - Component [detail]: Защитная втулка  | designation М10-00.00.003  | pos. 5  | Масса: 0.0193569; Раздел спецификации: Детали; Форматы листов документа: A4; source file: ..\М10-00.00.003 - Защитная втулка.cdw, ..\М10-00.00.003 - Защитная втулка.m3d
  - Component [detail]: Импеллер Магна10  | designation М10-00.00.001  | pos. 3  | Масса: 0.169927; Раздел спецификации: Детали; Форматы листов документа: A3; source file: ..\М10-00.00.001 - Импеллер Магна10.cdw, ..\М10-00.00.001 - Импеллер Магна10.m3d
  - Component [detail]: Крышка  | designation М10-00.00.002  | pos. 4
      Материал: Полипропилен  ГОСТ 26996-86 (density 900 kg/m3)
      Масса: 0.324102
      Раздел спецификации: Детали
      Форматы листов документа: 4xA4
      Примечание: @100~)4xA4
      source file: ..\М10-00.00.002 - Крышка.cdw, ..\М10-00.00.002 - Крышка.m3d
  - Component [assembly]: Вал  | designation М10-00.15.000-0,55кВт-475  | pos. 1
      Материал: Полипропилен  ГОСТ 26996-86 (density 900 kg/m3)
      Масса: 0.642468
      Раздел спецификации: Сборочные единицы
      Форматы листов документа: 2xA3
      Примечание: @100~)2xA3
      source file: ..\М10-00.15.000 - Вал.a3d
  - Component [assembly]: Корпус полипропилен  | designation М10-00.20.000-PP-475  | pos. 2  | Материал: Полипропилен  ГОСТ 26996-86 (density 900 kg/m3); Масса: 5.45783; Раздел спецификации: Сборочные единицы; Форматы листов документа: 3xA3; Примечание: @100~)3xA3@101~)3xA3
- Part/product: Магна Ins 10-PP-425-0,75кВт  | designation М10-00.00.000-PP-425-0,75кВт
    Масса: 15.0386
  - Component [assembly]: Корпус полипропилен 425 0,75кВт  | designation М10-00.20.000-PP-425-0,75кВт  | pos. 2  | Материал: Полипропилен  ГОСТ 26996-86 (density 900 kg/m3); Масса: 4.95604; Раздел спецификации: Сборочные единицы; Форматы листов документа: 3xA3; Примечание: @100~)3xA3@101~)3xA3
  - Component [assembly]: Вал  | designation М10-00.15.000-0,75кВт-425  | pos. 1
      Материал: Полипропилен  ГОСТ 26996-86 (density 900 kg/m3)
      Масса: 0.908797
      Раздел спецификации: Сборочные единицы
      Форматы листов документа: 2xA3
      Примечание: @100~)2xA3
      source file: ..\М10-00.15.000 - Вал.a3d
  - Component [detail]: Крышка  | designation М10-00.00.002  | pos. 4
      Материал: Полипропилен  ГОСТ 26996-86 (density 900 kg/m3)
      Масса: 0.324102
      Раздел спецификации: Детали
      Форматы листов документа: 4xA4
      Примечание: @100~)4xA4
      source file: ..\М10-00.00.002 - Крышка.cdw, ..\М10-00.00.002 - Крышка.m3d
  - Component [detail]: Импеллер Магна10  | designation М10-00.00.001  | pos. 3  | Масса: 0.169927; Раздел спецификации: Детали; Форматы листов документа: A3; source file: ..\М10-00.00.001 - Импеллер Магна10.cdw, ..\М10-00.00.001 - Импеллер Магна10.m3d
  - Component [detail]: Защитная втулка  | designation М10-00.00.003  | pos. 5  | Масса: 0.0193569; Раздел спецификации: Детали; Форматы листов документа: A4; source file: ..\М10-00.00.003 - Защитная втулка.cdw, ..\М10-00.00.003 - Защитная втулка.m3d
  - Component [detail]: Втулка ответная  | designation М10А-00.00.003-01  | pos. 6  | Масса: 0.031838; Раздел спецификации: Детали; Форматы листов документа: A4; Примечание: Заим.; source file: ..\..\..\..\..\..\AquaProf\АкваProf 190\3Д модель\М10А-00.00.003 - Втулка ответная.m3d, ..\М10А-00.00.003-01 - Втулка ответная.cdw
  - Component [standard]: Шайба C.10.21 ГОСТ 11371-78  | qty 8  | pos. 11  | Материал: Сталь 12Х18Н10Т ГОСТ 5632-72 (density 1000 kg/m3); Масса: 0.003438; Раздел спецификации: Стандартные изделия; Рассекать на разрезах: no; additional columns: Сталь 12Х18Н10Т ГОСТ 5632-72
  - Component [standard]: Шайба 10 ГОСТ 6402-70  | qty 4  | pos. 10  | Масса: 0.00201; Раздел спецификации: Стандартные изделия; Примечание: Нерж.; Рассекать на разрезах: no; additional columns: 10; Без указания материала
  - Component [standard]: Гайка М10x1,25-6H(S16) ГОСТ 5915-70  | qty 4  | pos. 9  | Масса: 0.01022; Раздел спецификации: Стандартные изделия; Рассекать на разрезах: no; additional columns: М10x1,25-6H (S16); Сталь 12Х18Н10Т ГОСТ 5632-72
  - Component [standard]: Болт М10x1,25-6gx60 (S16) ГОСТ 7798-70  | qty 4  | pos. 8  | Масса: 0.0467; Раздел спецификации: Стандартные изделия; Рассекать на разрезах: no; additional columns: Сталь 12Х18Н10Т ГОСТ 5632-72
  - Component [detail]: Заглушка @2~25 FV PPR ф. "FV-Plast"  | qty 4  | pos. 12  | Материал: Полипропилен  ГОСТ 26996-86 (density 900 kg/m3); Масса: 0.0161976; Раздел спецификации: Прочие изделия
- Part/product: Магна Ins 10-PP-425-1,1кВт  | designation М10-00.00.000-PP-425-1,1кВт
    Масса: 15.0361
  - Component [assembly]: Корпус полипропилен 425 1,1кВт  | designation М10-00.20.000-PP-425-1,1кВт  | pos. 2  | Материал: Полипропилен  ГОСТ 26996-86 (density 900 kg/m3); Масса: 4.95604; Раздел спецификации: Сборочные единицы; Форматы листов документа: 3xA3; Примечание: @100~)3xA3@101~)3xA3
  - Component [detail]: Электродвигатель / АИР 71B2 IM 3081 IP55 ф."Элком"  | pos. 14  | Масса: 8.3; Раздел спецификации: Прочие изделия; Примечание: См. заказ
  - Component [assembly]: Вал  | designation М10-00.15.000-1,1кВт-425  | pos. 1
      Материал: Полипропилен  ГОСТ 26996-86 (density 900 kg/m3)
      Масса: 0.906297
      Раздел спецификации: Сборочные единицы
      Форматы листов документа: 2xA3
      Примечание: @100~)2xA3
      source file: ..\М10-00.15.000 - Вал.a3d
  - Component [detail]: Крышка  | designation М10-00.00.002  | pos. 4
      Материал: Полипропилен  ГОСТ 26996-86 (density 900 kg/m3)
      Масса: 0.324102
      Раздел спецификации: Детали
      Форматы листов документа: 4xA4
      Примечание: @100~)4xA4
      source file: ..\М10-00.00.002 - Крышка.cdw, ..\М10-00.00.002 - Крышка.m3d
  - Component [detail]: Импеллер Магна10  | designation М10-00.00.001  | pos. 3  | Масса: 0.169927; Раздел спецификации: Детали; Форматы листов документа: A3; source file: ..\М10-00.00.001 - Импеллер Магна10.cdw, ..\М10-00.00.001 - Импеллер Магна10.m3d
  - Component [detail]: Защитная втулка  | designation М10-00.00.003  | pos. 5  | Масса: 0.0193569; Раздел спецификации: Детали; Форматы листов документа: A4; source file: ..\М10-00.00.003 - Защитная втулка.cdw, ..\М10-00.00.003 - Защитная втулка.m3d
  - Component [detail]: Втулка ответная  | designation М10А-00.00.003-01  | pos. 6  | Масса: 0.031838; Раздел спецификации: Детали; Форматы листов документа: A4; Примечание: Заим.; source file: ..\..\..\..\..\..\AquaProf\АкваProf 190\3Д модель\М10А-00.00.003 - Втулка ответная.m3d, ..\М10А-00.00.003-01 - Втулка ответная.cdw
  - Component [standard]: Шайба C.10.21 ГОСТ 11371-78  | qty 8  | pos. 11  | Материал: Сталь 12Х18Н10Т ГОСТ 5632-72 (density 1000 kg/m3); Масса: 0.003438; Раздел спецификации: Стандартные изделия; Рассекать на разрезах: no; additional columns: Сталь 12Х18Н10Т ГОСТ 5632-72
  - Component [standard]: Шайба 10 ГОСТ 6402-70  | qty 4  | pos. 10  | Масса: 0.00201; Раздел спецификации: Стандартные изделия; Примечание: Нерж.; Рассекать на разрезах: no; additional columns: 10; Без указания материала
  - Component [standard]: Гайка М10x1,25-6H(S16) ГОСТ 5915-70  | qty 4  | pos. 9  | Масса: 0.01022; Раздел спецификации: Стандартные изделия; Рассекать на разрезах: no; additional columns: М10x1,25-6H (S16); Сталь 12Х18Н10Т ГОСТ 5632-72
  - Component [standard]: Болт М10x1,25-6gx60 (S16) ГОСТ 7798-70  | qty 4  | pos. 8  | Масса: 0.0467; Раздел спецификации: Стандартные изделия; Рассекать на разрезах: no; additional columns: Сталь 12Х18Н10Т ГОСТ 5632-72
  - Component [detail]: Заглушка @2~25 FV PPR ф. "FV-Plast"  | qty 4  | pos. 12  | Материал: Полипропилен  ГОСТ 26996-86 (density 900 kg/m3); Масса: 0.0161976; Раздел спецификации: Прочие изделия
